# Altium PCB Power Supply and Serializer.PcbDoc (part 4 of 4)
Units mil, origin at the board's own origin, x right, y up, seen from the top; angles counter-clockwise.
Board outline 986 x 985 mil, 8 copper layers (TOP, GND1, INNER1, GND2, PWR1, INNER2, GND3, BOTTOM), stack 60.4 mil thick; 91 components, 64 nets, 288 pads, 200 vias.
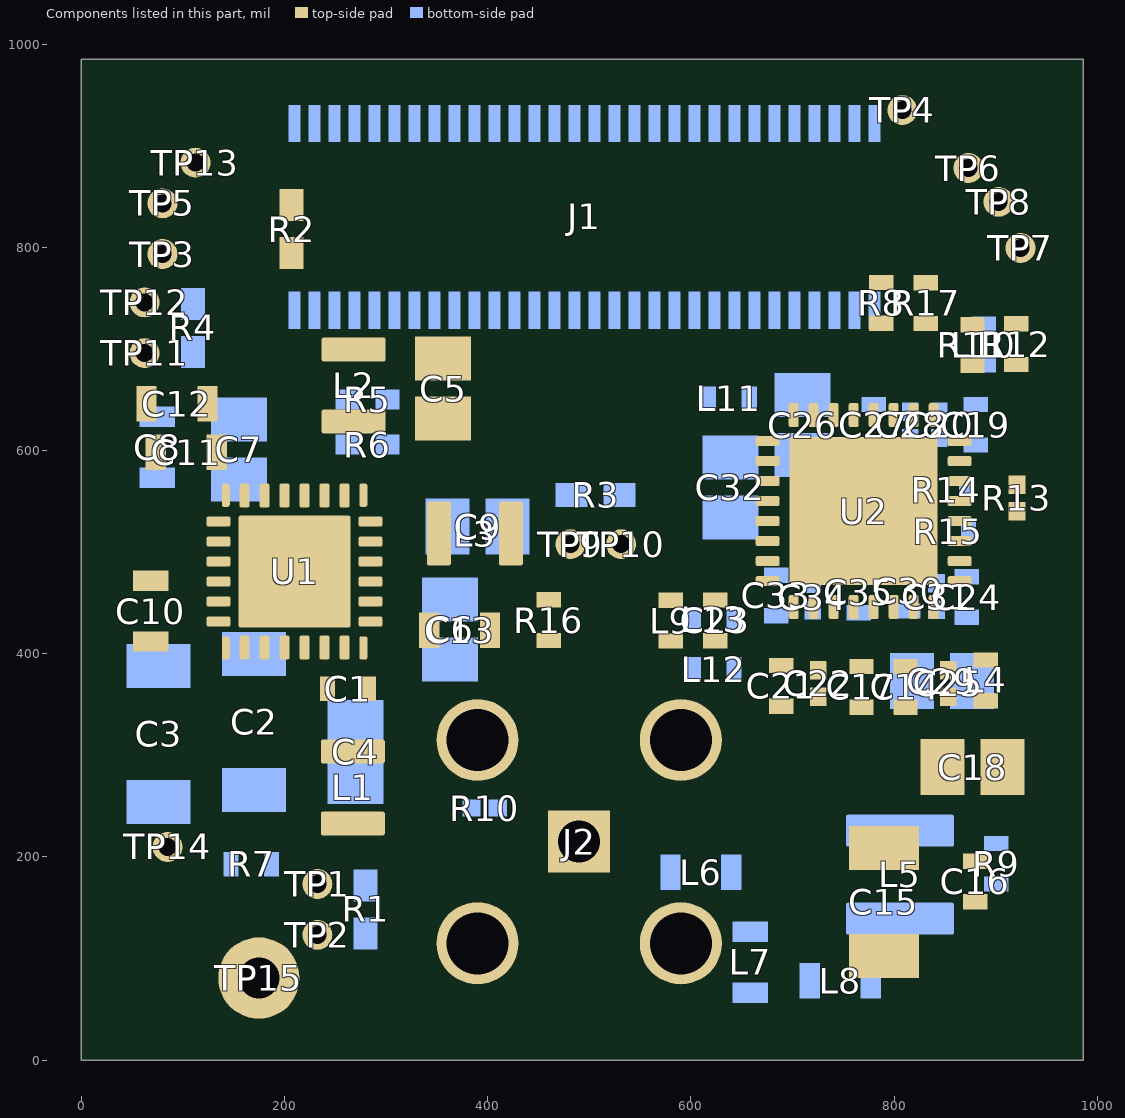
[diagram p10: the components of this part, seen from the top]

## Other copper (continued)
GND3:
  pour cut-out: 533.66,215.8 532.16,227.15 527.78,237.73 520.81,246.81 511.73,253.78 501.15,258.16 489.8,259.66 478.45,258.16 467.87,253.78 458.79,246.81 451.82,237.73 447.44,227.15 445.94,215.8 447.44,204.45 451.82,193.87 458.79,184.79 467.87,177.82 478.45,173.44 489.8,171.94 501.15,173.44 511.73,177.82 520.81,184.79 527.78,193.87 532.16,204.45 533.66,215.8
  pour cut-out: 439.41,315.8 437.72,328.64 432.77,340.61 424.88,350.88 414.61,358.77 402.64,363.72 389.8,365.41 376.96,363.72 364.99,358.77 354.72,350.88 346.83,340.61 341.88,328.64 340.19,315.8 341.88,302.96 346.83,290.99 354.72,280.72 364.99,272.83 376.96,267.88 389.8,266.19 402.64,267.88 414.61,272.83 424.88,280.72 432.77,290.99 437.72,302.96 439.41,315.8
  pour cut-out: 338.63,263.3 337.39,269.55 333.85,274.85 328.55,278.39 322.3,279.63 316.05,278.39 310.75,274.85 307.21,269.55 305.97,263.3 307.21,257.05 310.75,251.75 316.05,248.21 322.3,246.97 328.55,248.21 333.85,251.75 337.39,257.05 338.63,263.3
  pour cut-out: 201.59,220.3 200.51,225.77 197.41,230.41 192.77,233.51 187.3,234.59 181.83,233.51 177.19,230.41 174.09,225.77 173.01,220.3 174.09,214.83 177.19,210.19 181.83,207.09 187.3,206.01 192.77,207.09 197.41,210.19 200.51,214.83 201.59,220.3
  pour cut-out: 239.09,253.3 238.01,258.77 234.91,263.41 230.27,266.51 224.8,267.59 219.33,266.51 214.69,263.41 211.59,258.77 210.51,253.3 211.59,247.83 214.69,243.19 219.33,240.09 224.8,239.01 230.27,240.09 234.91,243.19 238.01,247.83 239.09,253.3
  pour cut-out: 934.09,658.3 933.01,663.77 929.91,668.41 925.27,671.51 919.8,672.59 914.33,671.51 909.69,668.41 906.59,663.77 905.51,658.3 906.59,652.83 909.69,648.19 914.33,645.09 919.8,644.01 925.27,645.09 929.91,648.19 933.01,652.83 934.09,658.3
  pour cut-out: 327.09,680.8 326.01,686.27 322.91,690.91 318.27,694.01 312.8,695.09 307.33,694.01 302.69,690.91 299.59,686.27 298.51,680.8 299.59,675.33 302.69,670.69 307.33,667.59 312.8,666.51 318.27,667.59 322.91,670.69 326.01,675.33 327.09,680.8
  pour cut-out: 109.26,209.8 107.4,219.16 102.1,227.1 94.16,232.4 84.8,234.26 75.44,232.4 67.5,227.1 62.2,219.16 60.34,209.8 62.2,200.44 67.5,192.5 75.44,187.2 84.8,185.34 94.16,187.2 102.1,192.5 107.4,200.44 109.26,209.8
  pour cut-out: 83.63,308.3 82.39,314.55 78.85,319.85 73.55,323.39 67.3,324.63 61.05,323.39 55.75,319.85 52.21,314.55 50.97,308.3 52.21,302.05 55.75,296.75 61.05,293.21 67.3,291.97 73.55,293.21 78.85,296.75 82.39,302.05 83.63,308.3
  pour cut-out: 126.13,308.3 124.89,314.55 121.35,319.85 116.05,323.39 109.8,324.63 103.55,323.39 98.25,319.85 94.71,314.55 93.47,308.3 94.71,302.05 98.25,296.75 103.55,293.21 109.8,291.97 116.05,293.21 121.35,296.75 124.89,302.05 126.13,308.3
  pour cut-out: 127.09,427.9 126.01,433.37 122.91,438.01 118.27,441.11 112.8,442.19 107.33,441.11 102.69,438.01 99.59,433.37 98.51,427.9 99.59,422.43 102.69,417.79 107.33,414.69 112.8,413.61 118.27,414.69 122.91,417.79 126.01,422.43 127.09,427.9
  pour cut-out: 161.43,220.8 160.35,226.27 157.25,230.91 152.61,234.01 147.14,235.09 141.67,234.01 137.03,230.91 133.93,226.27 132.85,220.8 133.93,215.33 137.03,210.69 141.67,207.59 147.14,206.51 152.61,207.59 157.25,210.69 160.35,215.33 161.43,220.8
  pour cut-out: 168.63,308.3 167.39,314.55 163.85,319.85 158.55,323.39 152.3,324.63 146.05,323.39 140.75,319.85 137.21,314.55 135.97,308.3 137.21,302.05 140.75,296.75 146.05,293.21 152.3,291.97 158.55,293.21 163.85,296.75 167.39,302.05 168.63,308.3
  pour cut-out: 211.13,308.3 209.89,314.55 206.35,319.85 201.05,323.39 194.8,324.63 188.55,323.39 183.25,319.85 179.71,314.55 178.47,308.3 179.71,302.05 183.25,296.75 188.55,293.21 194.8,291.97 201.05,293.21 206.35,296.75 209.89,302.05 211.13,308.3
  pour cut-out: 214.25,574.8 213.17,580.27 210.07,584.91 205.43,588.01 199.96,589.09 194.49,588.01 189.85,584.91 186.75,580.27 185.67,574.8 186.75,569.33 189.85,564.69 194.49,561.59 199.96,560.51 205.43,561.59 210.07,564.69 213.17,569.33 214.25,574.8
  pour cut-out: 233.93,379.8 232.85,385.27 229.75,389.91 225.11,393.01 219.64,394.09 214.17,393.01 209.53,389.91 206.43,385.27 205.35,379.8 206.43,374.33 209.53,369.69 214.17,366.59 219.64,365.51 225.11,366.59 229.75,369.69 232.85,374.33 233.93,379.8
  pour cut-out: 275.8,575.8 274.72,581.27 271.62,585.91 266.98,589.01 261.51,590.09 256.04,589.01 251.4,585.91 248.3,581.27 247.22,575.8 248.3,570.33 251.4,565.69 256.04,562.59 261.51,561.51 266.98,562.59 271.62,565.69 274.72,570.33 275.8,575.8
  pour cut-out: 293.63,890.8 292.39,897.05 288.85,902.35 283.55,905.89 277.3,907.13 271.05,905.89 265.75,902.35 262.21,897.05 260.97,890.8 262.21,884.55 265.75,879.25 271.05,875.71 277.3,874.47 283.55,875.71 288.85,879.25 292.39,884.55 293.63,890.8
  pour cut-out: 266.13,865.8 264.89,872.05 261.35,877.35 256.05,880.89 249.8,882.13 243.55,880.89 238.25,877.35 234.71,872.05 233.47,865.8 234.71,859.55 238.25,854.25 243.55,850.71 249.8,849.47 256.05,850.71 261.35,854.25 264.89,859.55 266.13,865.8
  pour cut-out: 439.41,115.8 437.72,128.64 432.77,140.61 424.88,150.88 414.61,158.77 402.64,163.72 389.8,165.41 376.96,163.72 364.99,158.77 354.72,150.88 346.83,140.61 341.88,128.64 340.19,115.8 341.88,102.96 346.83,90.99 354.72,80.72 364.99,72.83 376.96,67.88 389.8,66.19 402.64,67.88 414.61,72.83 424.88,80.72 432.77,90.99 437.72,102.96 439.41,115.8
  pour cut-out: 341.39,885.8 340.31,891.27 337.21,895.91 332.57,899.01 327.1,900.09 321.63,899.01 316.99,895.91 313.89,891.27 312.81,885.8 313.89,880.33 316.99,875.69 321.63,872.59 327.1,871.51 332.57,872.59 337.21,875.69 340.31,880.33 341.39,885.8
  pour cut-out: 477.09,385.8 476.01,391.27 472.91,395.91 468.27,399.01 462.8,400.09 457.33,399.01 452.69,395.91 449.59,391.27 448.51,385.8 449.59,380.33 452.69,375.69 457.33,372.59 462.8,371.51 468.27,372.59 472.91,375.69 476.01,380.33 477.09,385.8
  pour cut-out: 639.41,315.8 637.72,328.64 632.77,340.61 624.88,350.88 614.61,358.77 602.64,363.72 589.8,365.41 576.96,363.72 564.99,358.77 554.72,350.88 546.83,340.61 541.88,328.64 540.19,315.8 541.88,302.96 546.83,290.99 554.72,280.72 564.99,272.83 576.96,267.88 589.8,266.19 602.64,267.88 614.61,272.83 624.88,280.72 632.77,290.99 637.72,302.96 639.41,315.8
  pour cut-out: 561.13,412.71 559.89,418.96 556.35,424.26 551.05,427.8 544.8,429.04 538.55,427.8 533.25,424.26 529.71,418.96 528.47,412.71 529.71,406.46 533.25,401.16 538.55,397.62 544.8,396.38 551.05,397.62 556.35,401.16 559.89,406.46 561.13,412.71
  pour cut-out: 561.13,452.87 559.89,459.12 556.35,464.42 551.05,467.96 544.8,469.2 538.55,467.96 533.25,464.42 529.71,459.12 528.47,452.87 529.71,446.62 533.25,441.32 538.55,437.78 544.8,436.54 551.05,437.78 556.35,441.32 559.89,446.62 561.13,452.87
  pour cut-out: 695.69,893.3 694.61,898.77 691.51,903.41 686.87,906.51 681.4,907.59 675.93,906.51 671.29,903.41 668.19,898.77 667.11,893.3 668.19,887.83 671.29,883.19 675.93,880.09 681.4,879.01 686.87,880.09 691.51,883.19 694.61,887.83 695.69,893.3
  pour cut-out: 724.09,410.8 723.01,416.27 719.91,420.91 715.27,424.01 709.8,425.09 704.33,424.01 699.69,420.91 696.59,416.27 695.51,410.8 696.59,405.33 699.69,400.69 704.33,397.59 709.8,396.51 715.27,397.59 719.91,400.69 723.01,405.33 724.09,410.8
  pour cut-out: 774.25,415.8 773.17,421.27 770.07,425.91 765.43,429.01 759.96,430.09 754.49,429.01 749.85,425.91 746.75,421.27 745.67,415.8 746.75,410.33 749.85,405.69 754.49,402.59 759.96,401.51 765.43,402.59 770.07,405.69 773.17,410.33 774.25,415.8
  pour cut-out: 735.09,893.3 734.01,898.77 730.91,903.41 726.27,906.51 720.8,907.59 715.33,906.51 710.69,903.41 707.59,898.77 706.51,893.3 707.59,887.83 710.69,883.19 715.33,880.09 720.8,879.01 726.27,880.09 730.91,883.19 734.01,887.83 735.09,893.3
  pour cut-out: 774.49,893.3 773.41,898.77 770.31,903.41 765.67,906.51 760.2,907.59 754.73,906.51 750.09,903.41 746.99,898.77 745.91,893.3 746.99,887.83 750.09,883.19 754.73,880.09 760.2,879.01 765.67,880.09 770.31,883.19 773.41,887.83 774.49,893.3
  pour cut-out: 935.09,590.8 934.01,596.27 930.91,600.91 926.27,604.01 920.8,605.09 915.33,604.01 910.69,600.91 907.59,596.27 906.51,590.8 907.59,585.33 910.69,580.69 915.33,577.59 920.8,576.51 926.27,577.59 930.91,580.69 934.01,585.33 935.09,590.8
  pour cut-out: 908.09,550.64 907.01,556.11 903.91,560.75 899.27,563.85 893.8,564.93 888.33,563.85 883.69,560.75 880.59,556.11 879.51,550.64 880.59,545.17 883.69,540.53 888.33,537.43 893.8,536.35 899.27,537.43 903.91,540.53 907.01,545.17 908.09,550.64
  pour cut-out: 323.63,205.8 322.39,212.05 318.85,217.35 313.55,220.89 307.3,222.13 301.05,220.89 295.75,217.35 292.21,212.05 290.97,205.8 292.21,199.55 295.75,194.25 301.05,190.71 307.3,189.47 313.55,190.71 318.85,194.25 322.39,199.55 323.63,205.8
  text ".Layer_Name" at 577,-858.49 h60
BOTTOM:
  region net NetL6_2: 632.65,204.48 649.95,204.48 649.95,204.49 650.74,204.46 651.52,204.35 652.29,204.18 653.05,203.94 653.78,203.64 654.48,203.28 655.15,202.85 655.77,202.37 656.36,201.84 656.89,201.25 657.37,200.63 657.8,199.96 658.16,199.26 658.46,198.53 658.7,197.77 658.87,197 658.98,196.22 659.01,195.43 659.01,195.42 659.01,174.18 658.98,173.39 658.87,172.61 658.7,171.84 658.46,171.08 658.16,170.35 657.8,169.65 657.37,168.98 656.89,168.36 656.36,167.77 655.77,167.24 655.15,166.76 654.48,166.33 653.78,165.97 653.05,165.67 652.29,165.43 651.52,165.26 650.74,165.15 649.95,165.12 632.65,165.12 631.86,165.15 631.08,165.26 630.31,165.43 629.55,165.67 628.82,165.97 628.12,166.33 627.45,166.76 626.83,167.24 626.24,167.77 625.71,168.36 625.23,168.98 624.8,169.65 624.44,170.35 624.14,171.08 623.9,171.84 623.73,172.61 623.62,173.39 623.59,174.18 623.59,195.42 623.62,196.21 623.73,196.99 623.9,197.77 624.13,198.52 624.43,199.25 624.8,199.95 625.22,200.62 625.7,201.25 626.24,201.83 626.82,202.36 627.45,202.85 628.11,203.27 628.81,203.64 629.54,203.94 630.3,204.18 631.07,204.35 631.85,204.45 632.64,204.49 632.65,204.48
  region net NetL6_2: 677.98,136.35 677.98,119.05 677.99,119.05 677.96,118.26 677.85,117.48 677.68,116.71 677.44,115.95 677.14,115.22 676.78,114.52 676.35,113.85 675.87,113.23 675.34,112.64 674.75,112.11 674.13,111.63 673.46,111.2 672.76,110.84 672.03,110.54 671.27,110.3 670.5,110.13 669.72,110.02 668.93,109.99 668.92,109.99 647.68,109.99 646.89,110.02 646.11,110.13 645.34,110.3 644.58,110.54 643.85,110.84 643.15,111.2 642.48,111.63 641.86,112.11 641.27,112.64 640.74,113.23 640.26,113.85 639.83,114.52 639.47,115.22 639.17,115.95 638.93,116.71 638.76,117.48 638.65,118.26 638.62,119.05 638.62,136.35 638.65,137.14 638.76,137.92 638.93,138.7 639.16,139.45 639.46,140.18 639.83,140.88 640.25,141.55 640.73,142.18 641.27,142.76 641.85,143.29 642.48,143.78 643.14,144.2 643.84,144.57 644.57,144.87 645.33,145.11 646.1,145.28 646.88,145.38 647.67,145.42 647.68,145.41 668.92,145.41 668.92,145.42 669.71,145.39 670.49,145.28 671.27,145.11 672.02,144.88 672.75,144.58 673.45,144.21 674.12,143.79 674.75,143.31 675.33,142.77 675.86,142.19 676.35,141.56 676.77,140.9 677.14,140.2 677.44,139.47 677.68,138.71 677.85,137.94 677.95,137.16 677.99,136.37 677.98,136.35
  region net NetC32_1: 728.07,447.53 728.07,438.09 728.05,437.71 728,437.34 727.92,436.97 727.81,436.61 727.66,436.26 727.49,435.92 727.29,435.61 727.06,435.31 726.8,435.03 726.52,434.77 726.22,434.54 725.9,434.34 725.57,434.17 725.22,434.02 724.86,433.91 724.49,433.83 724.12,433.78 723.74,433.76 715.86,433.76 715.48,433.78 715.11,433.83 714.74,433.91 714.38,434.02 714.03,434.17 713.69,434.34 713.38,434.54 713.08,434.77 712.8,435.03 712.54,435.31 712.31,435.61 712.11,435.92 711.94,436.26 711.79,436.61 711.68,436.97 711.6,437.34 711.55,437.71 711.53,438.09 711.53,447.53 711.55,447.91 711.59,448.28 711.67,448.65 711.79,449.01 711.93,449.36 712.11,449.7 712.31,450.02 712.54,450.32 712.79,450.59 713.07,450.85 713.37,451.08 713.69,451.28 714.02,451.46 714.37,451.61 714.73,451.72 715.1,451.8 715.47,451.85 715.85,451.87 715.86,451.86 723.74,451.86 723.74,451.87 724.12,451.85 724.49,451.8 724.86,451.72 725.22,451.61 725.57,451.46 725.9,451.29 726.22,451.09 726.52,450.86 726.8,450.6 727.06,450.32 727.29,450.02 727.49,449.7 727.66,449.37 727.81,449.02 727.92,448.66 728,448.29 728.05,447.92 728.07,447.54 728.07,447.53
  region net DGND: 728.07,473.51 728.07,464.07 728.05,463.69 728.01,463.32 727.92,462.95 727.81,462.59 727.67,462.24 727.49,461.9 727.29,461.58 727.06,461.28 726.81,461.01 726.53,460.75 726.23,460.52 725.91,460.32 725.58,460.14 725.23,459.99 724.87,459.88 724.5,459.8 724.13,459.75 723.75,459.73 723.74,459.74 715.86,459.74 715.86,459.73 715.48,459.75 715.11,459.8 714.74,459.88 714.38,459.99 714.03,460.14 713.69,460.31 713.38,460.51 713.08,460.74 712.8,461 712.54,461.28 712.31,461.58 712.11,461.89 711.94,462.23 711.79,462.58 711.68,462.94 711.6,463.31 711.55,463.68 711.53,464.06 711.53,464.07 711.53,473.51 711.55,473.89 711.6,474.26 711.68,474.63 711.79,474.99 711.94,475.34 712.11,475.67 712.31,475.99 712.54,476.29 712.8,476.57 713.08,476.83 713.38,477.06 713.69,477.26 714.03,477.43 714.38,477.58 714.74,477.69 715.11,477.77 715.48,477.82 715.86,477.84 723.74,477.84 724.12,477.82 724.49,477.77 724.86,477.69 725.22,477.58 725.57,477.43 725.9,477.26 726.22,477.06 726.52,476.83 726.8,476.57 727.06,476.29 727.29,475.99 727.49,475.67 727.66,475.34 727.81,474.99 727.92,474.63 728,474.26 728.05,473.89 728.07,473.51
  region net NetC26_1: 807.53,633.57 807.53,643.01 807.55,643.39 807.59,643.76 807.67,644.13 807.79,644.49 807.93,644.84 808.11,645.18 808.31,645.5 808.54,645.8 808.79,646.07 809.07,646.33 809.37,646.56 809.69,646.76 810.02,646.94 810.37,647.09 810.73,647.2 811.1,647.28 811.47,647.33 811.85,647.35 811.86,647.34 819.74,647.34 819.74,647.35 820.12,647.33 820.49,647.28 820.86,647.2 821.22,647.09 821.57,646.94 821.9,646.77 822.22,646.57 822.52,646.34 822.8,646.08 823.06,645.8 823.29,645.5 823.49,645.18 823.66,644.85 823.81,644.5 823.92,644.14 824,643.77 824.05,643.4 824.07,643.02 824.07,643.01 824.07,633.57 824.05,633.19 824.01,632.82 823.92,632.45 823.81,632.09 823.67,631.74 823.49,631.4 823.29,631.08 823.06,630.78 822.81,630.51 822.53,630.25 822.23,630.02 821.91,629.82 821.58,629.64 821.23,629.49 820.87,629.38 820.5,629.3 820.13,629.25 819.75,629.23 819.74,629.24 811.86,629.24 811.86,629.23 811.48,629.25 811.11,629.3 810.74,629.38 810.38,629.49 810.03,629.64 809.69,629.81 809.38,630.01 809.08,630.24 808.8,630.5 808.54,630.78 808.31,631.08 808.11,631.39 807.94,631.73 807.79,632.08 807.68,632.44 807.6,632.81 807.55,633.18 807.53,633.56 807.53,633.57
  region net DGND: 807.53,607.59 807.53,617.03 807.55,617.41 807.59,617.78 807.67,618.15 807.79,618.51 807.93,618.86 808.11,619.2 808.31,619.52 808.54,619.82 808.79,620.09 809.07,620.35 809.37,620.58 809.69,620.78 810.02,620.96 810.37,621.11 810.73,621.22 811.1,621.3 811.47,621.35 811.85,621.37 811.86,621.36 819.74,621.36 819.74,621.37 820.12,621.35 820.49,621.3 820.86,621.22 821.22,621.11 821.57,620.96 821.9,620.79 822.22,620.59 822.52,620.36 822.8,620.1 823.06,619.82 823.29,619.52 823.49,619.2 823.66,618.87 823.81,618.52 823.92,618.16 824,617.79 824.05,617.42 824.07,617.04 824.07,617.03 824.07,607.59 824.05,607.21 824.01,606.84 823.92,606.47 823.81,606.11 823.67,605.76 823.49,605.42 823.29,605.1 823.06,604.8 822.81,604.53 822.53,604.27 822.23,604.04 821.91,603.84 821.58,603.66 821.23,603.51 820.87,603.4 820.5,603.32 820.13,603.27 819.75,603.25 819.74,603.26 811.86,603.26 811.86,603.25 811.48,603.27 811.11,603.32 810.74,603.4 810.38,603.51 810.03,603.66 809.69,603.83 809.38,604.03 809.08,604.26 808.8,604.52 808.54,604.8 808.31,605.1 808.11,605.41 807.94,605.75 807.79,606.1 807.68,606.46 807.6,606.83 807.55,607.2 807.53,607.58 807.53,607.59
  region net NetC19_1: 836.03,633.57 836.03,643.01 836.05,643.39 836.09,643.76 836.17,644.13 836.29,644.49 836.43,644.84 836.61,645.18 836.81,645.5 837.04,645.8 837.29,646.07 837.57,646.33 837.87,646.56 838.19,646.76 838.52,646.94 838.87,647.09 839.23,647.2 839.6,647.28 839.97,647.33 840.35,647.35 840.36,647.34 848.24,647.34 848.24,647.35 848.62,647.33 848.99,647.28 849.36,647.2 849.72,647.09 850.07,646.94 850.4,646.77 850.72,646.57 851.02,646.34 851.3,646.08 851.56,645.8 851.79,645.5 851.99,645.18 852.16,644.85 852.31,644.5 852.42,644.14 852.5,643.77 852.55,643.4 852.57,643.02 852.57,643.01 852.57,633.57 852.55,633.19 852.51,632.82 852.42,632.45 852.31,632.09 852.17,631.74 851.99,631.4 851.79,631.08 851.56,630.78 851.31,630.51 851.03,630.25 850.73,630.02 850.41,629.82 850.08,629.64 849.73,629.49 849.37,629.38 849,629.3 848.63,629.25 848.25,629.23 848.24,629.24 840.36,629.24 840.36,629.23 839.98,629.25 839.61,629.3 839.24,629.38 838.88,629.49 838.53,629.64 838.19,629.81 837.88,630.01 837.58,630.24 837.3,630.5 837.04,630.78 836.81,631.08 836.61,631.39 836.44,631.73 836.29,632.08 836.18,632.44 836.1,632.81 836.05,633.18 836.03,633.56 836.03,633.57
  region net DGND: 836.03,607.59 836.03,617.03 836.05,617.41 836.09,617.78 836.17,618.15 836.29,618.51 836.43,618.86 836.61,619.2 836.81,619.52 837.04,619.82 837.29,620.09 837.57,620.35 837.87,620.58 838.19,620.78 838.52,620.96 838.87,621.11 839.23,621.22 839.6,621.3 839.97,621.35 840.35,621.37 840.36,621.36 848.24,621.36 848.24,621.37 848.62,621.35 848.99,621.3 849.36,621.22 849.72,621.11 850.07,620.96 850.4,620.79 850.72,620.59 851.02,620.36 851.3,620.1 851.56,619.82 851.79,619.52 851.99,619.2 852.16,618.87 852.31,618.52 852.42,618.16 852.5,617.79 852.55,617.42 852.57,617.04 852.57,617.03 852.57,607.59 852.55,607.21 852.51,606.84 852.42,606.47 852.31,606.11 852.17,605.76 851.99,605.42 851.79,605.1 851.56,604.8 851.31,604.53 851.03,604.27 850.73,604.04 850.41,603.84 850.08,603.66 849.73,603.51 849.37,603.4 849,603.32 848.63,603.27 848.25,603.25 848.24,603.26 840.36,603.26 840.36,603.25 839.98,603.27 839.61,603.32 839.24,603.4 838.88,603.51 838.53,603.66 838.19,603.83 837.88,604.03 837.58,604.26 837.3,604.52 837.04,604.8 836.81,605.1 836.61,605.41 836.44,605.75 836.29,606.1 836.18,606.46 836.1,606.83 836.05,607.2 836.03,607.58 836.03,607.59
  region net NetL5_1: 770.27,117.54 740.74,135.26 740.74,162.82 870.66,162.82 870.66,135.26 841.13,117.54 770.27,117.54
  region net VDD_VIN: 841.13,247.46 870.66,229.74 870.66,202.18 740.74,202.18 740.74,229.74 770.27,247.46 841.13,247.46
  region net DOUTN_C: 404.57,256.57 414.01,256.57 414.39,256.55 414.76,256.5 415.13,256.42 415.49,256.31 415.84,256.16 416.17,255.99 416.49,255.79 416.79,255.56 417.07,255.3 417.33,255.02 417.56,254.72 417.76,254.4 417.93,254.07 418.08,253.72 418.19,253.36 418.27,252.99 418.32,252.62 418.34,252.24 418.34,244.36 418.32,243.98 418.27,243.61 418.19,243.24 418.08,242.88 417.93,242.53 417.76,242.19 417.56,241.88 417.33,241.58 417.07,241.3 416.79,241.04 416.49,240.81 416.17,240.61 415.84,240.44 415.49,240.29 415.13,240.18 414.76,240.1 414.39,240.05 414.01,240.03 404.57,240.03 404.19,240.05 403.82,240.09 403.45,240.17 403.09,240.29 402.74,240.43 402.4,240.61 402.08,240.81 401.78,241.04 401.51,241.29 401.25,241.57 401.02,241.87 400.82,242.19 400.64,242.52 400.49,242.87 400.38,243.23 400.3,243.6 400.25,243.97 400.23,244.35 400.24,244.36 400.24,252.24 400.23,252.24 400.25,252.62 400.3,252.99 400.38,253.36 400.49,253.72 400.64,254.07 400.81,254.4 401.01,254.72 401.24,255.02 401.5,255.3 401.78,255.56 402.08,255.79 402.39,255.99 402.73,256.16 403.08,256.31 403.44,256.42 403.81,256.5 404.18,256.55 404.56,256.57 404.57,256.57
  region net DGND: 378.59,256.57 388.03,256.57 388.41,256.55 388.78,256.51 389.15,256.42 389.51,256.31 389.86,256.17 390.2,255.99 390.52,255.79 390.82,255.56 391.09,255.31 391.35,255.03 391.58,254.73 391.78,254.41 391.96,254.08 392.11,253.73 392.22,253.37 392.3,253 392.35,252.63 392.37,252.25 392.36,252.24 392.36,244.36 392.37,244.36 392.35,243.98 392.3,243.61 392.22,243.24 392.11,242.88 391.96,242.53 391.79,242.19 391.59,241.88 391.36,241.58 391.1,241.3 390.82,241.04 390.52,240.81 390.2,240.61 389.87,240.44 389.52,240.29 389.16,240.18 388.79,240.1 388.42,240.05 388.04,240.03 388.03,240.03 378.59,240.03 378.21,240.05 377.84,240.1 377.47,240.18 377.11,240.29 376.76,240.44 376.42,240.61 376.11,240.81 375.81,241.04 375.53,241.3 375.27,241.58 375.04,241.88 374.84,242.19 374.67,242.53 374.52,242.88 374.41,243.24 374.33,243.61 374.28,243.98 374.26,244.36 374.26,252.24 374.28,252.62 374.33,252.99 374.41,253.36 374.52,253.72 374.67,254.07 374.84,254.4 375.04,254.72 375.27,255.02 375.53,255.3 375.81,255.56 376.11,255.79 376.42,255.99 376.76,256.16 377.11,256.31 377.47,256.42 377.84,256.5 378.21,256.55 378.59,256.57
  region net NetR7_2: 141.04,207.17 153.24,207.17 153.79,207.15 154.33,207.07 154.87,206.96 155.39,206.79 155.9,206.58 156.39,206.33 156.85,206.03 157.29,205.7 157.69,205.32 158.07,204.92 158.4,204.48 158.7,204.02 158.95,203.53 159.16,203.02 159.33,202.5 159.44,201.96 159.52,201.42 159.54,200.87 159.54,184.73 159.52,184.18 159.44,183.64 159.33,183.1 159.16,182.58 158.95,182.07 158.7,181.58 158.4,181.12 158.07,180.68 157.69,180.28 157.29,179.9 156.85,179.57 156.39,179.27 155.9,179.02 155.39,178.81 154.87,178.64 154.33,178.53 153.79,178.45 153.24,178.43 141.04,178.43 140.49,178.45 139.95,178.53 139.41,178.64 138.89,178.81 138.38,179.02 137.89,179.27 137.43,179.57 136.99,179.9 136.59,180.28 136.21,180.68 135.88,181.12 135.58,181.58 135.33,182.07 135.12,182.58 134.95,183.1 134.84,183.64 134.76,184.18 134.74,184.73 134.74,200.87 134.76,201.42 134.84,201.96 134.95,202.5 135.12,203.02 135.33,203.53 135.58,204.02 135.88,204.48 136.21,204.92 136.59,205.32 136.99,205.7 137.43,206.03 137.89,206.33 138.38,206.58 138.89,206.79 139.41,206.96 139.95,207.07 140.49,207.15 141.04,207.17
  region net VREG: 181.2,207.17 193.4,207.17 193.95,207.15 194.49,207.07 195.03,206.96 195.55,206.79 196.06,206.58 196.55,206.33 197.01,206.03 197.45,205.7 197.85,205.32 198.23,204.92 198.56,204.48 198.86,204.02 199.11,203.53 199.32,203.02 199.49,202.5 199.6,201.96 199.68,201.42 199.7,200.87 199.7,184.73 199.68,184.18 199.6,183.64 199.49,183.1 199.32,182.58 199.11,182.07 198.86,181.58 198.56,181.12 198.23,180.68 197.85,180.28 197.45,179.9 197.01,179.57 196.55,179.27 196.06,179.02 195.55,178.81 195.03,178.64 194.49,178.53 193.95,178.45 193.4,178.43 181.2,178.43 180.65,178.45 180.11,178.53 179.57,178.64 179.05,178.81 178.54,179.02 178.05,179.27 177.59,179.57 177.15,179.9 176.75,180.28 176.37,180.68 176.04,181.12 175.74,181.58 175.49,182.07 175.28,182.58 175.11,183.1 175,183.64 174.92,184.18 174.9,184.73 174.9,200.87 174.92,201.42 175,201.96 175.11,202.5 175.28,203.02 175.49,203.53 175.74,204.02 176.04,204.48 176.37,204.92 176.75,205.32 177.15,205.7 177.59,206.03 178.05,206.33 178.54,206.58 179.05,206.79 179.57,206.96 180.11,207.07 180.65,207.15 181.2,207.17
  region net NetL7_2: 677.98,73.35 677.98,56.05 677.99,56.05 677.96,55.26 677.85,54.48 677.68,53.7 677.45,52.95 677.15,52.22 676.78,51.52 676.36,50.85 675.88,50.22 675.34,49.64 674.76,49.11 674.13,48.62 673.47,48.2 672.77,47.83 672.04,47.53 671.28,47.29 670.51,47.12 669.73,47.02 668.94,46.98 668.92,46.99 647.68,46.99 647.68,46.98 646.89,47.01 646.11,47.12 645.34,47.29 644.58,47.53 643.85,47.83 643.15,48.19 642.48,48.62 641.86,49.1 641.27,49.63 640.74,50.22 640.26,50.84 639.83,51.51 639.47,52.21 639.17,52.94 638.93,53.7 638.76,54.47 638.65,55.25 638.62,56.04 638.62,56.05 638.62,73.35 638.65,74.14 638.76,74.92 638.93,75.7 639.16,76.45 639.46,77.18 639.83,77.88 640.25,78.55 640.73,79.18 641.27,79.76 641.85,80.29 642.48,80.78 643.14,81.2 643.84,81.57 644.57,81.87 645.33,82.11 646.1,82.28 646.88,82.38 647.67,82.42 647.68,82.41 668.92,82.41 668.92,82.42 669.71,82.39 670.49,82.28 671.27,82.11 672.02,81.88 672.75,81.58 673.45,81.21 674.12,80.79 674.75,80.31 675.33,79.77 675.86,79.19 676.35,78.56 676.77,77.9 677.14,77.2 677.44,76.47 677.68,75.71 677.85,74.94 677.95,74.16 677.99,73.37 677.98,73.35
  region net NetL7_2: 706.75,97.78 724.05,97.78 724.84,97.75 725.62,97.64 726.4,97.47 727.15,97.24 727.88,96.94 728.58,96.57 729.25,96.15 729.88,95.67 730.46,95.13 730.99,94.55 731.48,93.92 731.9,93.26 732.27,92.56 732.57,91.83 732.81,91.07 732.98,90.3 733.08,89.52 733.12,88.73 733.11,88.72 733.11,67.48 733.12,67.48 733.09,66.69 732.98,65.91 732.81,65.13 732.58,64.38 732.28,63.65 731.91,62.95 731.49,62.28 731.01,61.65 730.47,61.07 729.89,60.54 729.26,60.05 728.6,59.63 727.9,59.26 727.17,58.96 726.41,58.72 725.64,58.55 724.86,58.45 724.07,58.41 724.05,58.42 706.75,58.42 706.75,58.41 705.96,58.44 705.18,58.55 704.41,58.72 703.65,58.96 702.92,59.26 702.22,59.62 701.55,60.05 700.93,60.53 700.34,61.06 699.81,61.65 699.33,62.27 698.9,62.94 698.54,63.64 698.24,64.37 698,65.13 697.83,65.9 697.72,66.68 697.69,67.47 697.69,67.48 697.69,88.72 697.72,89.51 697.83,90.29 698,91.06 698.24,91.82 698.54,92.55 698.9,93.25 699.33,93.92 699.81,94.54 700.34,95.13 700.93,95.66 701.55,96.14 702.22,96.57 702.92,96.93 703.65,97.23 704.41,97.47 705.18,97.64 705.96,97.75 706.75,97.78
  region net NetL5_1: 769.75,97.78 787.05,97.78 787.84,97.75 788.62,97.64 789.4,97.47 790.15,97.24 790.88,96.94 791.58,96.57 792.25,96.15 792.88,95.67 793.46,95.13 793.99,94.55 794.48,93.92 794.9,93.26 795.27,92.56 795.57,91.83 795.81,91.07 795.98,90.3 796.08,89.52 796.12,88.73 796.11,88.72 796.11,67.48 796.12,67.48 796.09,66.69 795.98,65.91 795.81,65.13 795.58,64.38 795.28,63.65 794.91,62.95 794.49,62.28 794.01,61.65 793.47,61.07 792.89,60.54 792.26,60.05 791.6,59.63 790.9,59.26 790.17,58.96 789.41,58.72 788.64,58.55 787.86,58.45 787.07,58.41 787.05,58.42 769.75,58.42 769.75,58.41 768.96,58.44 768.18,58.55 767.41,58.72 766.65,58.96 765.92,59.26 765.22,59.62 764.55,60.05 763.93,60.53 763.34,61.06 762.81,61.65 762.33,62.27 761.9,62.94 761.54,63.64 761.24,64.37 761,65.13 760.83,65.9 760.72,66.68 760.69,67.47 760.69,67.48 760.69,88.72 760.72,89.51 760.83,90.29 761,91.06 761.24,91.82 761.54,92.55 761.9,93.25 762.33,93.92 762.81,94.54 763.34,95.13 763.93,95.66 764.55,96.14 765.22,96.57 765.92,96.93 766.65,97.23 767.41,97.47 768.18,97.64 768.96,97.75 769.75,97.78
  pour cut-out: 109.06,209.8 107.21,219.08 101.95,226.95 94.08,232.21 84.8,234.06 75.52,232.21 67.65,226.95 62.39,219.08 60.54,209.8 62.39,200.52 67.65,192.65 75.52,187.39 84.8,185.54 94.08,187.39 101.95,192.65 107.21,200.52 109.06,209.8
  pour cut-out: 128.11,427.9 126.95,433.76 123.63,438.73 118.66,442.05 112.8,443.21 106.94,442.05 101.97,438.73 98.65,433.76 97.49,427.9 98.65,422.04 101.97,417.07 106.94,413.75 112.8,412.59 118.66,413.75 123.63,417.07 126.95,422.04 128.11,427.9
  pour cut-out: 234.95,379.8 233.79,385.66 230.47,390.63 225.5,393.95 219.64,395.11 213.78,393.95 208.81,390.63 205.49,385.66 204.33,379.8 205.49,373.94 208.81,368.97 213.78,365.65 219.64,364.49 225.5,365.65 230.47,368.97 233.79,373.94 234.95,379.8
  pour cut-out: 938.15,590.8 936.83,597.44 933.07,603.07 927.44,606.83 920.8,608.15 914.16,606.83 908.53,603.07 904.77,597.44 903.45,590.8 904.77,584.16 908.53,578.53 914.16,574.77 920.8,573.45 927.44,574.77 933.07,578.53 936.83,584.16 938.15,590.8
  text ".Layer_Name" at 577,-858.49 h60

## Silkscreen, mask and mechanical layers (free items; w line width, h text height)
Top Overlay:
  text "'.PRJ_Number'.PCB_Rev" at 1090,74 h108.27
  text ".Layer_Name" at 577,-858.49 h60
Bottom Overlay:
  text ".Layer_Name" at 577,-858.49 h60
Top Paste:
  drawing of 114 lines, arcs and shapes, not listed
  text ".Layer_Name" at 577,-858.49 h60
Bottom Paste:
  drawing of 80 lines, arcs and shapes, not listed
  text ".Layer_Name" at 577,-858.49 h60
Top Solder:
  drawing of 114 lines, arcs and shapes, not listed
  text ".Layer_Name" at 577,-858.49 h60
  text ".Layer_Name" at 577,-858.49 h60
Bottom Solder:
  drawing of 80 lines, arcs and shapes, not listed
  text ".Layer_Name" at 577,-858.49 h60
Drill Guide:
  text ".Layer_Name" at 577,-858.49 h60
M1 Board Outline:
  the board outline again, w3
  text ".Layer_Name" at 577,-858.49 h60
M2 Board Dimensions:
  rectangle: 0,-275 125,-150
  rectangle: 125,-400 500,-275
  lines w1: -110.7,2.5 423.95,2.5 ; -110.7,982.9 408.93,982.9 ; -100.2,465 -100.2,0 ; -100.2,485 -100.2,980.4 ; -95.7,471 -89.7,471 ; -95.7,475 -89.7,475 ; -92.7,472 -92.7,478 ; 2.3,-22.5 2.3,27.5 ; 2.3,590.66 2.3,1065.5 ; 447.3,1050 -0.2,1050 ; 479.3,1046 485.3,1046 ; 479.3,1050 485.3,1050 ; 482.3,1047 482.3,1053 ; 502.3,1050 980.2,1050 ; 982.7,609.98 982.7,1065.5 ; -100.2,0 -98.2,13 -102.2,13 -100.2,0 ; -100.2,980.4 -102.2,967.4 -98.2,967.4 -100.2,980.4 ; -0.2,1050 12.8,1052 12.8,1048 -0.2,1050 ; 980.2,1050 967.2,1048 967.2,1052 980.2,1050
  lines w7: 0,-275 1000,-275 ; 125,-400 125,-150 ; 250,-400 250,-150 ; 500,-400 500,-150 ; 750,-400 750,-150 ; 0,-400 1000,-400 1000,-150 0,-150 0,-400
  text "980" at 453.3,1046 h8
  text "5" at 490.3,1046 h8
  text "980" at -121.7,471 h8
  text "5" at -84.7,471 h8
  text ".Layer_Name" at 577,-858.49 h60
M3 3D STEP Top:
  text ".Layer_Name" at 577,-858.49 h60
M4 3D STEP Bottom:
  text ".Layer_Name" at 577,-858.49 h60
M5 Assembly Top:
  lines w10: -292,-930.17 6308,-930.17 ; -292,-726.83 6310,-726.83 ; -292,-523.5 -292,-1133.5 3713,-1133.5 6310,-1133.5 6310,-523.5 -291.5,-523.5 -291.5,-1133.5 1284,-1133.5 ; 2173,-1133.5 2173,-523.5 ; 3440,-726.83 3440,-523.5 ; 4280,-726.83 4280,-523.5 ; 4902,-1140 4902,-937.17
  text "COMPONENTS MARKED 'DNP' SHOULD NOT BE POPULATED." at 1153.5,-318.5 h60
  text "ASSEMBLY VARIANT:" at 1153,-434 h60
  text ".VariantName" at 2189,-434 h60
  text "PCB VIEWED FROM TOP SIDE" at -228.5,-655.67 h60
  text "BOARD #:" at 2248,-655.67 h60
  text ".PRJ_Number" at 2793.5,-655.67 h60
  text "REV:" at 3638,-655.67 h60
  text ".PCB_Rev" at 3929.5,-655.67 h60
  text "SVN REV:" at 4476,-655.67 h60
  text ".VersionControl_RevNumber" at 4982,-655.67 h60
  text "TID #:" at 2248,-859 h60
  text ".TID" at 2793.5,-859 h60
  text "PLOT NAME =" at -228.5,-1064.34 h60
  text ".plot_File_Name" at 577,-1064.34 h60
  text "GENERATED    :" at 2250,-1064.34 h60
  text ".Print_Date" at 3119.5,-1064.34 h60
  text ".Print_Time" at 3848.5,-1064.34 h60
  text "TEXAS INSTRUMENTS" at 5113,-1064.34 h60
M6 Assembly Bottom:
  lines w1: 784.8,263.3 797.66,260.55 ; 784.8,263.3 796.24,256.81 ; 784.8,263.3 797.66,260.55 ; 784.8,263.3 796.24,256.81 ; 796.24,256.81 797.66,260.55 ; 796.24,256.81 797.66,260.55
  lines w10: -292.5,-727.33 6309.5,-727.33 ; -290.5,-930.67 6309.5,-930.67 ; 1115.5,-1140.5 1115.5,-937.67 ; 1737.5,-727.33 1737.5,-524 ; 2577.5,-727.33 2577.5,-524 ; 3844.5,-1134 3844.5,-524 ; 4733.5,-1134 6309,-1134 6309,-524 -292.5,-524 -292.5,-1134 2304.5,-1134 6309.5,-1134 6309.5,-524
  text "COMPONENTS MARKED 'DNP' SHOULD NOT BE POPULATED." at 6102,-318 h60
  text ".VariantName" at 5058,-434 h60
  text "ASSEMBLY VARIANT:" at 6097,-434 h60
  text ".VersionControl_RevNumber" at 1035.5,-656.17 h60
  text "SVN REV:" at 1541.5,-656.17 h60
  text ".PCB_Rev" at 2088,-656.17 h60
  text "REV:" at 2379.5,-656.17 h60
  text ".PRJ_Number" at 3224,-656.17 h60
  text "BOARD #:" at 3769.5,-656.17 h60
  text "PCB VIEWED FROM BOTTOM SIDE" at 6246,-656.17 h60
  text ".TID" at 3224,-859.5 h60
  text "TID #:" at 3769.5,-859.5 h60
  text "TEXAS INSTRUMENTS" at 904.5,-1064.84 h60
  text ".Print_Time" at 2169,-1064.84 h60
  text ".Print_Date" at 2898,-1064.84 h60
  text "GENERATED    :" at 3767.5,-1064.84 h60
  text ".plot_File_Name" at 5440.5,-1064.84 h60
  text "PLOT NAME =" at 6246,-1064.84 h60
M9 Title Sheet:
  drawing of 57 lines, arcs and shapes, not listed
  text "1" at 739.84,8036.5 h70
  text "2" at 3235.5,8036.5 h70
  text "3" at 5724.84,8036.5 h70
  text "4" at 8231.51,8036.5 h70
  text "5" at 10730.5,8036.5 h70
  text "6" at 13235.5,8036.5 h70
  text "A" at -416.5,6893.5 h70
  text "A" at 14383.5,6893.5 h70
  text "B" at -416.5,4513.5 h70
  text "B" at 14383.5,4513.5 h70
  text "C" at -416.5,2138.5 h70
  text "C" at 14383.5,2138.5 h70
  text "PROJECT TITLE:" at 11343.5,277.5 h45
  text ".PRJ_Title" at 11393.5,144.17 h70
  text "DESIGNED FOR:" at 11343.5,-23.5 h45
  text ".PRJ_Customer" at 11393.5,-163.5 h70
  text "D" at -416.5,-231.5 h70
  text "D" at 14383.5,-231.5 h70
  text "FILE NAME:" at 11343.5,-323.5 h45
  text ".PCB_File_Name_No_Path" at 11393.5,-443.5 h70
  text "Texas Instruments (TI) and/or its licensors do not warrant the accuracy or completeness of this specification" at 6374,-605.34 h45
  text "ENGINEER:" at 11343.5,-613.5 h45
  text "LAYOUT BY:" at 12848.5,-613.5 h45
  text "or any information contained therein. TI and/or its licensors do not warrant that this design will meet" at 6329.01,-718 h45
  text ".PRJ_Engineer" at 11393.5,-768.49 h70
  text ".PCB_Layout" at 12899,-768.49 h70
  text "the specifications, will be suitable for your application or fit for any particular purpose, or will operate in" at 6329.01,-830.67 h45
  text ".Layer_Name" at 577,-858.49 h60
  text "ALTIUM DESIGNER VERSION:" at 12848.5,-923.5 h45
  text "an implementation. TI and/or its licensors do not warrant that the design is production worthy. You should" at 6329.01,-943.33 h45
  text "completely validate and test your design implementation to confirm the system functionality for your application." at 6374,-1056 h45
  text ".print_Scale" at 11393.5,-1056.83 h70
  text ".Application_BuildNumber" at 12899,-1056.83 h70
  text "1" at 739.84,-1263.5 h70
  text "2" at 3235.5,-1263.5 h70
  text "3" at 5724.84,-1263.5 h70
  text "4" at 8231.51,-1263.5 h70
  text "5" at 10730.5,-1263.5 h70
  text "6" at 13235.5,-1263.5 h70
M10 Fab Notes:
  drawing of 189 lines, arcs and shapes, not listed
  text "DESIGN INFORMATION" at 12382.02,6356.17 h60
  text "MIN. TRACK WIDTH:" at 11737.46,6224.05 h60
  text "8" at 12833.7,6224.05 h60
  text "MIL" at 12988.46,6224.05 h60
  text "MIN. CLEARANCE:" at 11737.46,6099.92 h60
  text "0.2" at 12773.7,6099.93 h60
  text "mm" at 12988.46,6099.92 h60
  text "MIN. VIA PAD SIZE:" at 11737.46,5975.8 h60
  text "24" at 12803.71,5975.8 h60
  text "MIL" at 12988.46,5975.8 h60
  text "0.05mm (2MIL)" at 12432.46,5845.9 h60
  text "MINIMUM ANNULAR RING" at 11408.23,5837.67 h60
  text "EXTERNAL" at 13140.46,5837.67 h60
  text "PER" at 11608.23,5727.55 h60
  text "IPC-D-275 CLASS 2 LEVEL C" at 11828.23,5727.54 h60
  text "MIL, HOLES" at 13316.46,5627.07 h60
  text "+/-" at 12924,5618.48 h60
  text "+/-" at 13778,5618.48 h60
  text "REGISTRATION TOLERANCES:" at 11408.23,5617.42 h60
  text "METAL" at 12608,5617.42 h60
  text "5" at 13184.2,5617.42 h60
  text "3" at 14017.2,5617.42 h60
  text "MIL" at 14133.46,5617.42 h60
  text "HOLE SIZE TOLERANCE (UNLESS OTHERWISE SPECIFIED):" at 11408.23,5519.1 h60
  text "+/-" at 13778,5516.23 h60
  text "3" at 14017.2,5515.17 h60
  text "MIL" at 14133.46,5515.17 h60
  text "MATERIAL:" at 11333.46,5377.52 h60
  text "FR-4 High Tg" at 12319.9,5249 h60
  text "X" at 12175.46,5241.01 h60
  text "FR-408" at 11754.46,5236.49 h60
  text "OTHER" at 13242.46,5236.49 h60
  text "62 MIL (1.6mm) +/-10%" at 12074.56,5093.46 h60
  text "X" at 11954.46,5091.01 h60
  text "THICKNESS:" at 11408.23,5085.24 h60
  text "OTHER" at 13359.46,5085.24 h60
  text "TOLERANCE:" at 11408.23,4946.92 h60
  text "X" at 12256.46,4946.92 h60
  text "ANSI IPC-6012 TYPE 3 CLASS 2" at 12434.48,4946.92 h60
  text "OTHER +/-" at 12434.46,4802.73 h60
  text "BOW & TWIST:" at 11408.23,4657.54 h60
  text "X" at 12256.46,4657.54 h60
  text "ANSI IPC-6012 TYPE 3 CLASS 2" at 12434.48,4657.54 h60
  text "OTHER +/-" at 12434.46,4510.85 h60
  text "DRILLING:" at 11333.46,4380.23 h60
  text "NC_DRILL FILES" at 13094.46,4275.04 h60
  text "REFERENCE:" at 11408.23,4271.1 h60
  text "X" at 12065.46,4271.01 h60
  text "AS SHOWN" at 12243.46,4271.1 h60
  text "X" at 12966.46,4271.1 h60
  text "OTHER" at 13392.46,4128.85 h60
  text "PTH COPPER THICKNESS:" at 11407.91,4125.32 h60
  text "X" at 12547.14,4125.32 h60
  text "20-30 um" at 12675.14,4125.32 h60
  text "BOARD FINISH:" at 11333.46,3977.73 h60
  text "SILKSCREEN:" at 11488.68,3867.6 h60
  text "X" at 12446.46,3867.6 h60
  text "TOP" at 12563.46,3867.6 h60
  text "X" at 12956.46,3867.6 h60
  text "BOTTOM" at 13074.46,3867.6 h60
  text "SILKSCREEN COLOR:" at 11488.68,3712.41 h60
  text "X" at 12445.46,3712.41 h60
  text "WHITE" at 12563.46,3712.41 h60
  text "OTHER" at 13074.46,3712.41 h60
  text "X" at 12576.46,3568.96 h60
  text "GREEN" at 12694.46,3568.96 h60
  text "OTHER" at 13312.46,3568.96 h60
  text "SOLDER RESIST COLOR:" at 11488.68,3562.1 h60
  text "X" at 12576.46,3414.71 h60
  text "MATTE" at 12694.46,3414.71 h60
  text "SEMI-GLOSS" at 13312,3414.07 h60
  text "IMMERSION GOLD (ENIG)" at 12394.46,3241.94 h60
  text "ENEPIG" at 13732,3234.72 h60
  text "SURFACE FINISH:" at 11333.46,3233.72 h60
  text "X" at 12216.46,3233.72 h60
  text "IMM. TIN/SILVER OR EQUIV" at 11663,3096.4 h60
  text "OTHER" at 13094.46,3092.47 h60
  text "ARRAY/PANEL:" at 11333.46,2937.09 h60
  text "CUT AND TRIM PER M1 BOARD OUTLINE" at 12394.46,2928.87 h60
  text "N.C. ROUTE" at 12394.46,2792.9 h60
  text "X" at 13082.46,2792.9 h60
  text "V. SCORE" at 13260.46,2792.9 h60
  text "CERTIFICATION:" at 11333.46,2663.77 h60
  text "MATERIALS AND WORKMANSHIP FOR ALL PCBS" at 12058.46,2663.77 h60
  text "TO MEET OR EXCEED THE REQUIREMENTS OF:" at 12058.46,2569.71 h60
  text "X" at 11695.97,2441.08 h60
  text "ANSI IPC-A-600F CLASS ->" at 11823.96,2441.08 h60
  text "X" at 13471.97,2441.08 h60
  text "2" at 13581.96,2441.08 h60
  text "1" at 13266.96,2439.58 h60
  text "3" at 13935.96,2439.58 h60
  text "X" at 12507.97,2293.39 h60
  text "RoHS" at 12635.96,2293.39 h60
  text "OTHER" at 13280.36,2293.39 h60
  text "PER ORDER" at 13677.42,2293.39 h60
  text "ALL BOARDS MUST MEET OR EXCEED UL94-V0 REQUIREMENTS." at 11361,2139.57 h60
  text "PCB MUST BEAR THE UL94V-0 UL REGISTERED MATERIAL ID NUMBER" at 11361,2023.5 h60
  text "ADDITIONAL REQUIREMENTS:" at 11333.46,1854.08 h60
  text "MICROSECTION:" at 11408.23,1746.95 h60
  text "YES" at 12313.96,1746.95 h60
  text "REQUIRED" at 13175.46,1602.62 h60
  text "BARE BOARD ELEC. TEST:" at 11408.23,1599.76 h60
  text "NONE" at 12713.96,1599.76 h60
  text "X" at 13057.46,1599.76 h60
  text "PER ORDER" at 13767.46,1599.76 h60
  text "XX MIL VIAS REQUIRE NON-CONDUCTIVE FILL AND PLANARIZE" at 11576.38,1394.82 h59
  text "XX MIL VIAS REQUIRE CONDUCTIVE FILL AND PLANARIZE" at 11584.38,1290.84 h60
  text "OUTER XX MIL TRACES REQUIRE 50 OHM SINGLE-ENDED IMPEDANCE" at 11583.39,1127.46 h58
  text "LAYER 2 & 3 (INNER LAYERS) XX MIL WIDE, XX MIL SPACE / TRACES REQUIRE 100 OHM DIFFERENTIAL IMPEDANCE" at 11575.39,891.74 h60
  text ".Layer_Name" at 577,-858.49 h60
M11 Gerber Information:
  lines w10: -292,-930.17 6308,-930.17 ; -292,-726.83 6310,-726.83 ; -292,-523.5 -292,-1133.5 3713,-1133.5 6310,-1133.5 6310,-523.5 -291.5,-523.5 -291.5,-1133.5 1284,-1133.5 ; 2173,-1133.5 2173,-523.5 ; 3440,-726.83 3440,-523.5 ; 4280,-726.83 4280,-523.5 ; 4902,-1140 4902,-937.17
  text "ALL ARTWORK VIEWED FROM TOP SIDE" at -228.5,-655.67 h60
  text "BOARD #:" at 2248,-655.67 h60
  text ".PRJ_Number" at 2793.5,-655.67 h60
  text "REV:" at 3638,-655.67 h60
  text ".PCB_Rev" at 3929.5,-655.67 h60
  text "SVN REV:" at 4476,-655.67 h60
  text ".VersionControl_RevNumber" at 4982,-655.67 h60
  text "LAYER NAME =" at -228.5,-858.49 h60
  text "TID #:" at 2248,-859 h60
  text ".TID" at 2793.5,-859 h60
  text "PLOT NAME =" at -228.5,-1064.34 h60
  text ".plot_File_Name" at 577,-1064.34 h60
  text "GENERATED    :" at 2250,-1064.34 h60
  text ".Print_Date" at 3119.5,-1064.34 h60
  text ".Print_Time" at 3848.5,-1064.34 h60
  text "TEXAS INSTRUMENTS" at 5113,-1064.34 h60
M12 Stackup:
  drawing of 503 lines, arcs and shapes, not listed
  text "Layer" at 6671.09,7632 h60
  text "Name" at 7081,7632 h60
  text "Material" at 8010.74,7632 h60
  text "Thickness" at 8870.51,7632 h60
  text "Constant" at 9520.35,7632 h60
  text "Board Layer Stack" at 10090.21,7632 h60
  text "1" at 6671.09,7512 h60
  text "Top Overlay" at 7081,7512 h60
  text "2" at 6671.09,7392 h60
  text "Top Solder" at 7081,7392 h60
  text "Solder Resist" at 8010.74,7392 h60
  text "0.40mil" at 8870.51,7392 h60
  text "3.5" at 9520.35,7392 h60
  text "3" at 6671.09,7272 h60
  text "TOP" at 7081,7272 h60
  text "Copper" at 8010.74,7272 h60
  text "2.10mil" at 8870.51,7272 h60
  text "4" at 6671.09,7152 h60
  text "Dielectric 1" at 7081,7152 h60
  text "FR-4" at 8010.74,7152 h60
  text "3.20mil" at 8870.51,7152 h60
  text "3.8" at 9520.35,7152 h60
  text "5" at 6671.09,7032 h60
  text "GND1" at 7081,7032 h60
  text "Copper" at 8010.74,7032 h60
  text "1.30mil" at 8870.51,7032 h60
  text "6" at 6671.09,6912 h60
  text "Dielectric2" at 7081,6912 h60
  text "FR-4" at 8010.74,6912 h60
  text "5.00mil" at 8870.51,6912 h60
  text "3.8" at 9520.35,6912 h60
  text "7" at 6671.09,6792 h60
  text "INNER1" at 7081,6792 h60
  text "Copper" at 8010.74,6792 h60
  text "1.30mil" at 8870.51,6792 h60
  text "8" at 6671.09,6672 h60
  text "Dielectric3" at 7081,6672 h60
  text "FR-4" at 8010.74,6672 h60
  text "9.00mil" at 8870.51,6672 h60
  text "3.8" at 9520.35,6672 h60
  text "9" at 6671.09,6552 h60
  text "GND2" at 7081,6552 h60
  text "Copper" at 8010.74,6552 h60
  text "1.30mil" at 8870.51,6552 h60
  text "10" at 6671.09,6432 h60
  text "Dielectric4" at 7081,6432 h60
  text "FR-4" at 8010.74,6432 h60
  text "14.00mil" at 8870.51,6432 h60
  text "3.8" at 9520.35,6432 h60
  text "11" at 6671.09,6312 h60
  text "PWR1" at 7081,6312 h60
  text "Copper" at 8010.74,6312 h60
  text "1.30mil" at 8870.51,6312 h60
  text "12" at 6671.09,6192 h60
  text "Dielectric5" at 7081,6192 h60
  text "FR-4" at 8010.74,6192 h60
  text "9.00mil" at 8870.51,6192 h60
  text "3.8" at 9520.35,6192 h60
  text "13" at 6671.09,6072 h60
  text "INNER2" at 7081,6072 h60
  text "Copper" at 8010.74,6072 h60
  text "1.30mil" at 8870.51,6072 h60
  text "14" at 6671.09,5952 h60
  text "Dielectric6" at 7081,5952 h60
  text "FR-4" at 8010.74,5952 h60
  text "5.00mil" at 8870.51,5952 h60
  text "3.8" at 9520.35,5952 h60
  text "15" at 6671.09,5832 h60
  text "GND3" at 7081,5832 h60
  text "Copper" at 8010.74,5832 h60
  text "1.30mil" at 8870.51,5832 h60
  text "16" at 6671.09,5712 h60
  text "Dielectric7" at 7081,5712 h60
  text "FR-4" at 8010.74,5712 h60
  text "3.20mil" at 8870.51,5712 h60
  text "3.8" at 9520.35,5712 h60
  text "17" at 6671.09,5592 h60
  text "BOTTOM" at 7081,5592 h60
  text "Copper" at 8010.74,5592 h60
  text "2.10mil" at 8870.51,5592 h60
  text "18" at 6671.09,5472 h60
  text "Bottom Solder" at 7081,5472 h60
  text "Solder Resist" at 8010.74,5472 h60
  text "0.40mil" at 8870.51,5472 h60
  text "3.5" at 9520.35,5472 h60
  text "19" at 6671.09,5352 h60
  text "Bottom Overlay" at 7081,5352 h60
  text ".Layer_Name" at 577,-858.49 h60
M13 Component Bodies Top:
  text ".Layer_Name" at 577,-858.49 h60
M14 Component Bodies Bottom:
  text ".Layer_Name" at 577,-858.49 h60
M15 Courtyards Top:
  text ".Layer_Name" at 577,-858.49 h60
M16 Courtyards Bottom:
  text ".Layer_Name" at 577,-858.49 h60
Drill Drawing:
  circle w10: c5363.72,2598.36 r27.63
  lines w10: 5336.09,2750.31 5391.34,2750.31 5363.72,2695.06 5336.09,2750.31 ; 5336.09,2819.38 5391.34,2819.38 5391.34,2874.63 5336.09,2874.63 5336.09,2819.38 ; 5336.09,2971.32 5363.72,2943.7 5391.34,2971.32 5363.72,2998.95 5336.09,2971.32 ; 5336.09,3068.02 5336.09,3081.83 5349.9,3095.64 5336.09,3109.46 5336.09,3123.27 5349.9,3123.27 5363.72,3109.46 5377.53,3123.27 5391.34,3123.27 5391.34,3109.46 5377.53,3095.64 5391.34,3081.83 5391.34,3068.02 5377.53,3068.02 5363.72,3081.83 5349.9,3068.02 5336.09,3068.02 ; 5336.09,3206.15 5349.9,3206.15 5349.9,3192.34 5377.53,3192.34 5377.53,3206.15 5391.34,3206.15 5391.34,3233.78 5377.53,3233.78 5377.53,3247.59 5349.9,3247.59 5349.9,3233.78 5336.09,3233.78 5336.09,3206.15 ; 5336.09,3316.66 5363.72,3330.47 5391.34,3316.66 5377.53,3344.28 5391.34,3371.91 5363.72,3358.1 5336.09,3371.91 5349.9,3344.28 5336.09,3316.66 ; 5347.14,2830.43 5380.29,2830.43 5380.29,2863.58 5347.14,2863.58 5347.14,2830.43
  lines w12: 5286,2533.44 8318.56,2533.44 ; 5286,3403.68 8318.56,3403.68 ; 5623.86,2409.12 5623.86,3528 ; 5955.86,2409.12 5955.86,3528 ; 6592.43,2409.12 6592.43,3528 ; 6851.57,2409.12 6851.57,3528 ; 7226.72,2409.12 7226.72,3528 ; 7752.13,2409.12 7752.13,3528 ; 5286,2409.12 8318.56,2409.12 8318.56,3528 5286,3528 5286,2409.12
  text "Symbol" at 5360.59,3440.98 h72
  text "Quantity" at 5661.16,3440.98 h72
  text "Finished Hole Size" at 5993.16,3440.98 h72
  text "Plated" at 6629.72,3440.98 h72
  text "Hole Type" at 6888.86,3440.98 h72
  text "Drill Layer Pair" at 7264.02,3440.98 h72
  text "Hole Tolerance" at 7789.43,3440.98 h72
  text "17" at 5661.16,3316.66 h60
  text "7.87mil (0.200mm)" at 5993.16,3316.66 h60
  text "PTH" at 6629.72,3316.66 h60
  text "Round" at 6888.86,3316.66 h60
  text "TOP - BOTTOM" at 7264.02,3316.66 h60
  text "147" at 5661.16,3192.34 h60
  text "8.00mil (0.203mm)" at 5993.16,3192.34 h60
  text "PTH" at 6629.72,3192.34 h60
  text "Round" at 6888.86,3192.34 h60
  text "TOP - BOTTOM" at 7264.02,3192.34 h60
  text "36" at 5661.16,3068.02 h60
  text "12.00mil (0.305mm)" at 5993.16,3068.02 h60
  text "PTH" at 6629.72,3068.02 h60
  text "Round" at 6888.86,3068.02 h60
  text "TOP - BOTTOM" at 7264.02,3068.02 h60
  text "14" at 5661.16,2943.7 h60
  text "17.72mil (0.450mm)" at 5993.16,2943.7 h60
  text "PTH" at 6629.72,2943.7 h60
  text "Round" at 6888.86,2943.7 h60
  text "TOP - BOTTOM" at 7264.02,2943.7 h60
  text "1" at 5661.16,2819.38 h60
  text "40.00mil (1.016mm)" at 5993.16,2819.38 h60
  text "PTH" at 6629.72,2819.38 h60
  text "Round" at 6888.86,2819.38 h60
  text "TOP - BOTTOM" at 7264.02,2819.38 h60
  text "1" at 5661.16,2695.06 h60
  text "41.34mil (1.050mm)" at 5993.16,2695.06 h60
  text "PTH" at 6629.72,2695.06 h60
  text "Round" at 6888.86,2695.06 h60
  text "TOP - BOTTOM" at 7264.02,2695.06 h60
  text "4" at 5661.16,2570.74 h60
  text "61.02mil (1.550mm)" at 5993.16,2570.74 h60
  text "PTH" at 6629.72,2570.74 h60
  text "Round" at 6888.86,2570.74 h60
  text "TOP - BOTTOM" at 7264.02,2570.74 h60
  text "220 Total" at 5661.16,2446.42 h60
  text ".Layer_Name" at 577,-858.49 h60
M17 Embedded Cavity:
  lines w1: 879.3,94.8 969.3,7.3 879.3,94.8 ; 879.3,94.8 890.02,87.17 ; 879.3,94.8 887.23,84.3 ; 879.3,94.8 890.02,87.17 ; 879.3,94.8 887.23,84.3 ; 887.23,84.3 890.02,87.17 ; 887.23,84.3 890.02,87.17 ; 917.3,80.8 1007.3,-6.7 917.3,80.8 ; 917.3,80.8 928.02,73.17 ; 917.3,80.8 925.23,70.3 ; 917.3,80.8 928.02,73.17 ; 917.3,80.8 925.23,70.3 ; 925.23,70.3 928.02,73.17 ; 925.23,70.3 928.02,73.17 ; -183.7,14.8 158.3,14.8 -183.7,14.8 ; -145.7,0.8 196.3,0.8 -145.7,0.8
  text ".Layer_Name" at 577,-858.49 h60
M18 Embedded Assembly:
  text ".Layer_Name" at 577,-858.49 h60
M19 Embedded Keepout:
  text ".Layer_Name" at 577,-858.49 h60
Mechanical 28:
  text "ASSEMBLY BOTTOM (VIEWED FROM BOTTOM SIDE)" at 941.8,-35.2 h25
  text "ASSEMBLY BOTTOM (VIEWED FROM BOTTOM SIDE)" at 979.8,-49.2 h25
Mechanical 29:
  text "SOLDERPASTE BOTTOM (VIEWED FROM BOTTOM SIDE)" at 941.8,-35.2 h25
  text "SOLDERPASTE BOTTOM (VIEWED FROM BOTTOM SIDE)" at 979.8,-49.2 h25
Mechanical 30:
  text "SOLDERMASK BOTTOM (VIEWED FROM BOTTOM SIDE)" at 941.8,-35.2 h25
  text "SOLDERMASK BOTTOM (VIEWED FROM BOTTOM SIDE)" at 979.8,-49.2 h25
Mechanical 31:
  text "SILKSCREEN BOTTOM (VIEWED FROM BOTTOM SIDE)" at 941.8,-35.2 h25
  text "SILKSCREEN BOTTOM (VIEWED FROM BOTTOM SIDE)" at 979.8,-49.2 h25
Mechanical 32:
  lines w1: -76.2,50.8 16423.8,50.8 -76.2,50.8 ; -38.2,36.8 16461.8,36.8 -38.2,36.8

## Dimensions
0,-400 to 1000,-400 on M2 Board Dimensions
